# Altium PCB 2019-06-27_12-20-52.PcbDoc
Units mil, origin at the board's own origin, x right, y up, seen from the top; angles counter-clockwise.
Board outline 2660 x 2720 mil, 4 copper layers (Top Layer, MidLayer1, MidLayer2, Bottom Layer); 29 components, 16 nets, 76 pads, 58 vias.
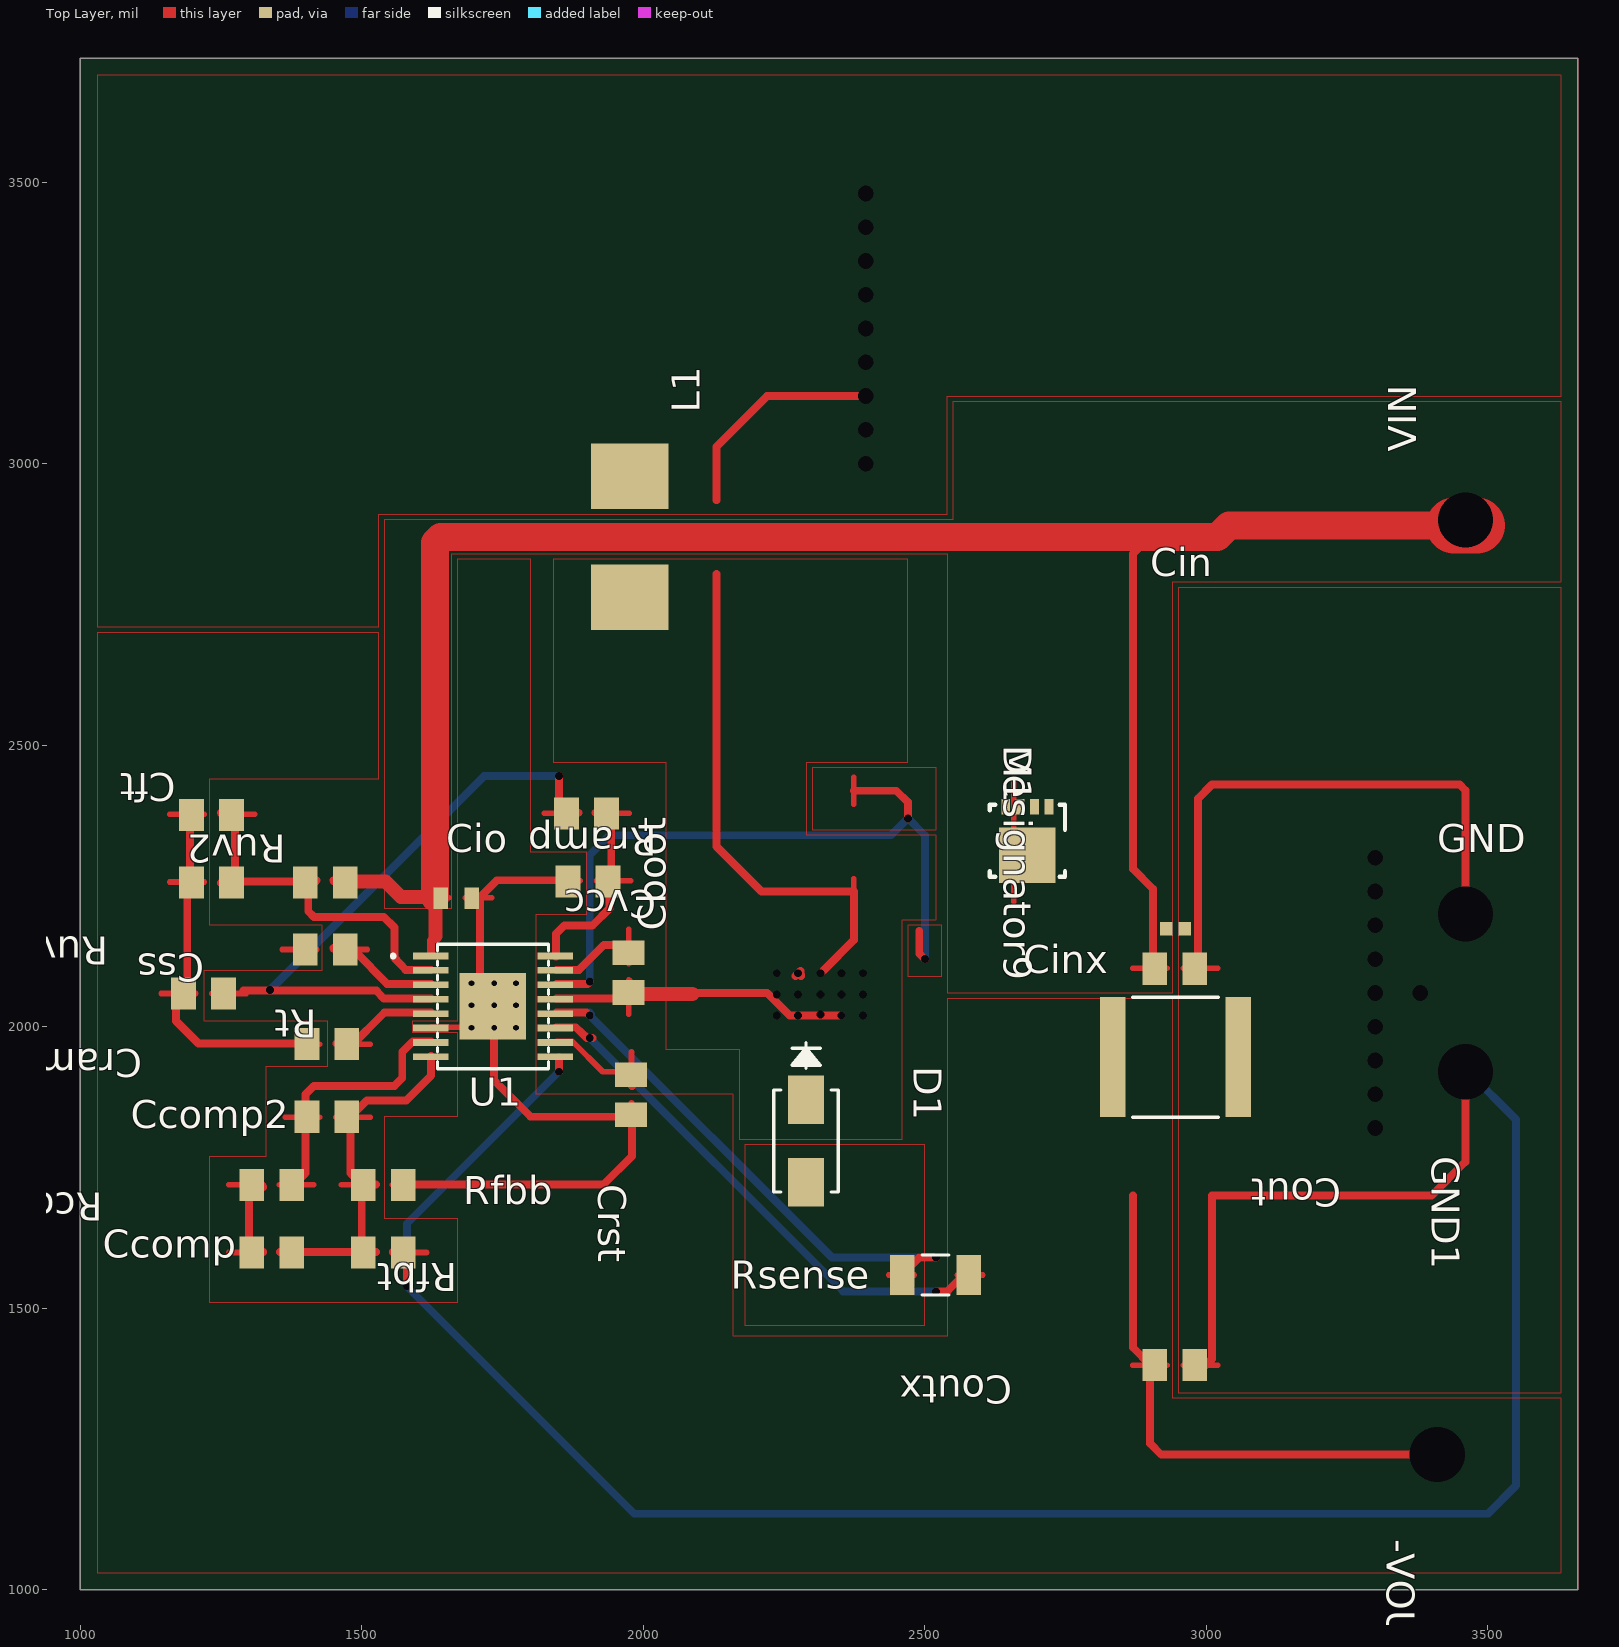
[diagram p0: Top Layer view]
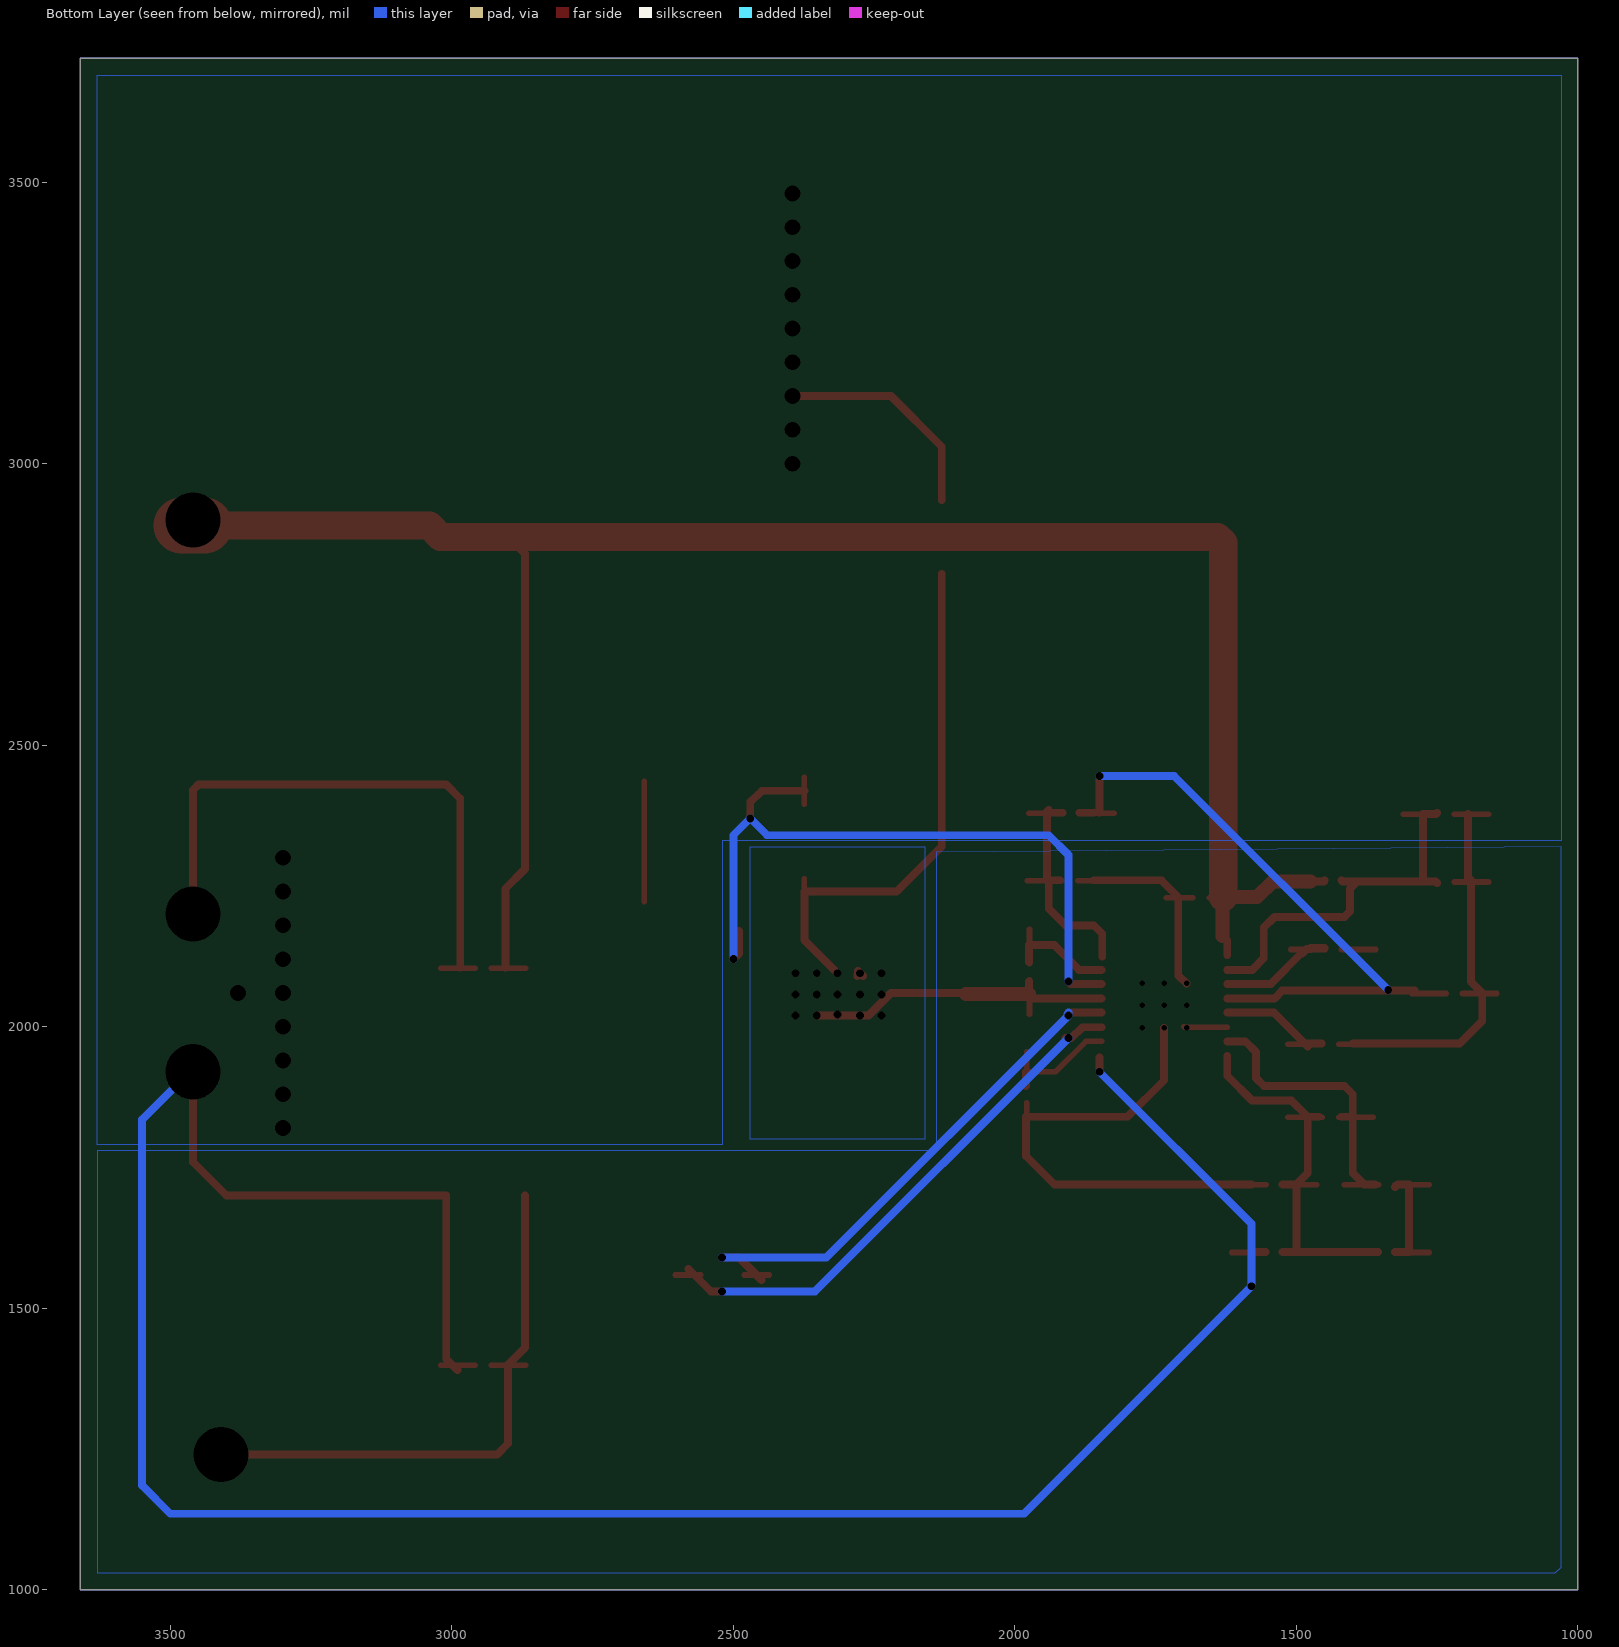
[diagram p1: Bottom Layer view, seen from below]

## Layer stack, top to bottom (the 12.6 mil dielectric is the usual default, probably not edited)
Top Layer: signal copper 1.4
Dielectric: core 12.6, FR-4, Dk 4.8
MidLayer1: signal copper 1.4
Dielectric: prepreg 12.6, FR-4, Dk 4.8
MidLayer2: signal copper 1.4
Dielectric: core 12.6, FR-4, Dk 4.8
Bottom Layer: signal copper 1.4

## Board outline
1000,1000 3660,1000 3660,3720 1000,3720

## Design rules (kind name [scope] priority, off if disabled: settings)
PlaneConnect [All] p0: scope1count=1 scope1_0_kind=Board scope1_0_value=Board scope2count=1 scope2_0_kind=Board scope2_0_value=Board commentlength=0 planeconnectstyle=Direct reliefexpansion=20 reliefentries=4 reliefconductorwidth=10 reliefairgap=10
PlaneConnect [All] p1: planeconnectstyle=Direct reliefexpansion=20 reliefentries=4 reliefconductorwidth=10 reliefairgap=10
PolygonConnect [All] p0: scope1count=1 scope1_0_kind=Board scope1_0_value=Board scope2count=1 scope2_0_kind=Board scope2_0_value=Board commentlength=0 connectstyle=Direct reliefconductorwidth=10 reliefentries=4 polygonreliefangle="90 Angle"
PolygonConnect [All] p1: connectstyle=Direct reliefconductorwidth=10 reliefentries=4 polygonreliefangle="90 Angle"

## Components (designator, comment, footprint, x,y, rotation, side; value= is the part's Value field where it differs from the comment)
-VOUT "" TP-1502 3409,1240 r270 top
Cboot "" 0805 1974,2096 r90 top
Ccomp "" 0805 1340,1599 r0 top
Ccomp2 "" 0805 1438,1840 r0 top
Cft "" 0805 1233,2376 r180 top
Cin "" 0402 2945,2174 r0 top
Cinx "" 0805 2944,2103 r0 top
Cio "" 0603 1668,2228 r0 top
Cout "" 2220_280 2945,1946 r180 top
Coutx "" 0805 2944,1399 r180 top
Cramp "" 0805 1219,2059 r180 top
Crst "" 0805 1978,1879 r270 top
Css "" 0805 1435,2137 r180 top
Cvcc "" 0805 1902,2258 r180 top
D1 "" SMA 2289,1797 r270 top
GND "" TP-1502 3459,2198 r0 top
GND1 "" TP-1502 3459,1918 r270 top
L1 "" WE-LHMI_7030 1976,2870 r90 top
M1 "" DNH0008A 2682,2330 r270 top
Rcomp "" 0805 1340,1719 r180 top
Rfbb "" 0805 1538,1719 r0 top
Rfbt "" 0805 1538,1599 r180 top
Rramp "" 0805 1899,2379 r180 top
Rsense "" 1206 2519,1559 r0 top
Rt "" 0805 1438,1969 r180 top
Ruv1 "" 0805 1233,2256 r180 top
Ruv2 "" 0805 1435,2256 r180 top
U1 "" MXA16A 1733,2036 r0 top
VIN "" TP-1502 3459,2899 r90 top

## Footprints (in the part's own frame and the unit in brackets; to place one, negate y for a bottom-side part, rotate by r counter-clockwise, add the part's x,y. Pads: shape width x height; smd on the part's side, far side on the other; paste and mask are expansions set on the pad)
0402 [mil]
  rect 22x24 smd: 1(-16.5,0) 2(16.5,0)
0603 [mil]
  rect 26x38 smd: 1(-27.5,0) 2(27.5,0)
0805 [mil]
  rect 44x57 smd: 1(-35.5,0) 2(35.5,0)
1206 [mil]
  rect 44x71 smd: 1(-59,0) 2(59,0)
  silkscreen extent -24,-36 24,36
2220_280 [mil]
  rect 45x213 smd: 1(-111.5,0) 2(111.5,0)
  silkscreen extent -76,-107 76,107
DNH0008A [mm]
  rect 0.7x0.4 smd: 1(-1.55,0.975) 2(-1.55,0.325) 3(-1.55,-0.325) 4(-1.55,-0.975) 5(1.55,-0.975) 6(1.55,-0.325) 7(1.55,0.325) 8(1.55,0.975)
  rect 2.51x2.55 smd: 9(0.645,0)
  silkscreen extent -1.62,-1.7 1.62,1.7
MXA16A [mm]
  rect 1.6x0.3 smd: 1(-2.8,2.275) 2(-2.8,1.625) 3(-2.8,0.975) 4(-2.8,0.325) 5(-2.8,-0.325) 6(-2.8,-0.975) 7(-2.8,-1.625) 8(-2.8,-2.275) 9(2.8,-2.275) 10(2.8,-1.625) 11(2.8,-0.975) 12(2.8,-0.325) 13(2.8,0.325) 14(2.8,0.975) 15(2.8,1.625) 16(2.8,2.275)
  rect 3x3 smd: 17(0,0)
  silkscreen extent -4.58,-2.8 2.5,2.8
SMA [mil]
  rect 86x64 smd: 1(-73,0) 2(73,0)
  silkscreen extent -174,-58 91,58
TP-1502 [mil]
  round 65 / inner round 0 / far side round 65 hole 32: 1(0,0)
WE-LHMI_7030 [mm]
  rect 2.95x3.5 smd: 1(-2.725,0) 2(2.725,0)

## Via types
v1: diameter 0, hole 14, Top Layer to Bottom Layer, 26 vias
v2: diameter 0, hole 28, Top Layer to Bottom Layer, 19 vias
v3: diameter 0, hole 10, Top Layer to Bottom Layer, 9 vias
v4: diameter 0, hole 98, Top Layer to Bottom Layer, 4 vias

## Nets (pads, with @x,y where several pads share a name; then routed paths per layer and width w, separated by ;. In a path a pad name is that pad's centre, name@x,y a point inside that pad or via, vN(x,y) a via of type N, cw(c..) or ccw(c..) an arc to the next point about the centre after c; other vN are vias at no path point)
0: -VOUT.1 Cft.2 Cio.2 Cout.2 Coutx.2 Cramp.2 Crst.2 Css.2 Cvcc.2 Rfbb.2 Rsense.2 Rt.2 Ruv1.2 U1.6 U1.11 U1.17 | length 4451.2
  Top Layer w10: 1144,2059 Cramp.2@1205,2059 ; 1159,2257 1220,2257 ; 1159,2377 1220,2377 ; 1359,2137 Css.2@1420,2137 ; 1364,1969 1425,1969 ; Rfbb.2@1554,1719 1615,1719 ; U1.6@1623,1999 1699,1999 U1.17@1700,2000 ; Cio.2@1684,2229 1731,2229 ; 1827,2259 Cvcc.2@1888,2259 ; 1979,1804 Crst.2@1979,1865 ; Rsense.2@2558,1559 2603,1559 ; 2869,1399 Coutx.2@2930,1399
  Top Layer w14: Cft.2@1195,2378 1195,2265 1190,2260 1190,2080 1170,2060 1170,2010 1210,1970 Rt.2@1400,1970 ; Rfbb.2@1580,1720 1930,1720 1980,1770 1980,1840 1800,1840 1735,1905 v3(1735,1998) ; v3(1695,2077) 1710,2091 1710,2230 1740,2260 Cvcc.2@1860,2260 ; U1.11@1846,1999 1880,1999 1900,1980 v1(1905,1980) 1910,1980 ; v1(2520,1530) 2540,1530 Rsense.2@2580,1570 ; 2870,1700 2870,1430 2900,1400 2900,1260 2920,1240 v4(3410,1240) -VOUT.1@3420,1240
  Bottom Layer w14: v1(1905,1980) 2355,1530 v1(2520,1530)
  other v3: 1695,1998 1774,1998 1695,2038 1735,2038 1774,2038 1735,2077 1774,2077
1: Ccomp2.2 Ccomp.2 Rfbb.1 Rfbt.2 U1.8 | length 915.5
  Top Layer w10: Ccomp.2@1354,1599 1415,1599 ; Ccomp2.2@1454,1839 1515,1839 ; 1464,1599 1525,1599 ; 1464,1719 1525,1719
  Top Layer w14: Ccomp.2@1355,1600 1380,1600 Rfbt.2@1500,1600 ; Ccomp2.2@1460,1840 Ccomp2.2@1480,1840 ; 1525,1600 Rfbt.2@1500,1600 ; 1525,1720 Rfbb.1@1500,1720 ; U1.8@1623,1948 1623,1913 1579,1869 1509,1869 Ccomp2.2@1480,1840 ; Ccomp2.2@1480,1840 1480,1740 Rfbb.1@1500,1720 ; Rfbt.2@1500,1600 Rfbb.1@1500,1720
2: Ccomp2.1 Rcomp.1 U1.7 | length 619.2
  Top Layer w10: Rcomp.1@1354,1719 1415,1719 ; 1364,1839 1425,1839
  Top Layer w14: Rcomp.1@1360,1720 1380,1720 1400,1740 Ccomp2.1@1400,1840 ; Ccomp2.1@1420,1840 Ccomp2.1@1400,1840 ; U1.7@1623,1974 1591,1974 1572,1955 1572,1909 1558,1895 1415,1895 1400,1880 Ccomp2.1@1400,1840
3: Cin.1 Cinx.1 Cio.1 M1.5 M1.6 M1.7 M1.8 M1.9 Ruv2.1 U1.1 VIN.1 | length 3966.1
  Top Layer w10: Ruv2.1@1449,2257 1510,2257 ; 1608,2229 1655,2229 ; 2658,2222 2658,2436 ; 2869,2104 Cinx.1@2930,2104
  Top Layer w14: Ruv2.1@1450,2260 1452,2258 Ruv2.1@1475,2258 ; U1.1@1623,2127 1623,2153 1631,2161 ; 2900,2870 2870,2840 2870,2420 2870,2280 2905,2245 Cinx.1@2905,2105
  Top Layer w25: Ruv2.1@1475,2258 1542,2258 1570,2230 Cio.1@1630,2230 ; 1631,2161 Cio.1@1631,2230
  Top Layer w50: Cio.1@1630,2230 1630,2750 1630,2860 1640,2870 1750,2870 2900,2870 3020,2870 3040,2890 VIN.1@3440,2890
  Top Layer w100: VIN.1@3440,2890 VIN.1@3480,2890
  other v4: 3460,2900
4: Crst.1 U1.10 | length 242.4
  Top Layer w10: U1.10@1846,1974 1874,1974 1928,1920 Crst.1@1980,1920 ; Crst.1@1979,1894 1979,1955
  Top Layer w14: Crst.1@1980,1895 Crst.1@1980,1920
5: Cin.2 Cinx.2 Cout.1 Coutx.1 GND1.1 GND.1 L1.2 Rfbt.1 U1.9 | length 6074
  Top Layer w10: Rfbt.1@1554,1599 1615,1599 ; Coutx.1@2959,1399 3020,1399 ; Cinx.2@2959,2104 3020,2104
  Top Layer w14: Rfbt.1@1555,1600 1580,1600 1580,1540 ; v1(1850,1920) U1.9@1850,1945 ; 2130,2935 2130,3030 2220,3120 v2(2395,3120) ; Cinx.2@2985,2105 2985,2405 3010,2430 3450,2430 3460,2420 v4(3460,2200) ; Coutx.1@2990,1390 3010,1410 3010,1700 3400,1700 3460,1760 v4(3460,1920)
  Bottom Layer w14: v1(1850,1920) 1580,1650 v1(1580,1539) 1984,1135 3500,1135 3550,1185 3550,1835 GND1.1@3465,1920
  other v2: 3300,1820 3300,1880 3300,1940 3300,2000 3300,2060 3380,2060 3300,2120 3300,2180 3300,2240 3300,2300 2395,3000 2395,3060 2395,3180 2395,3240 2395,3300 2395,3360 2395,3420 2395,3480
6: Cft.1 Ruv1.1 Ruv2.2 U1.2 | length 849.3
  Top Layer w10: Ruv1.1@1249,2257 1310,2257 ; Cft.1@1249,2377 1310,2377 ; 1359,2257 Ruv2.2@1420,2257
  Top Layer w14: Ruv1.1@1250,2255 1253,2258 Ruv1.1@1275,2258 ; Cft.1@1250,2380 1252,2378 1275,2378 Ruv1.1@1275,2258 ; Ruv2.2@1395,2258 1418,2258 Ruv2.2@1420,2260 ; U1.2@1623,2101 1578,2101 1558,2122 1558,2176 1539,2195 1415,2195 1405,2205 1405,2245 1392,2258 Ruv1.1@1275,2258
7: Cvcc.1 Rramp.1 U1.16 | length 501.1
  Top Layer w10: Rramp.1@1914,2379 1975,2379 ; Cvcc.1@1917,2259 1978,2259
  Top Layer w14: U1.16@1845,2125 1845,2165 1860,2180 1910,2180 1940,2210 Cvcc.1@1940,2260 ; Rramp.1@1915,2380 Rramp.1@1940,2380 ; Cvcc.1@1920,2260 Cvcc.1@1940,2260 ; Rramp.1@1940,2385 1943,2382 1943,2263 Cvcc.1@1940,2260 ; Cvcc.1@1943,2260 Cvcc.1@1940,2260
8: Cramp.1 Rramp.2 U1.4 | length 1221.5
  Top Layer w10: Cramp.1@1234,2059 1295,2059 ; 1824,2379 Rramp.2@1885,2379
  Top Layer w14: 1290,2064 1526,2064 1539,2050 U1.4@1623,2050 ; Rramp.2@1850,2380 v1(1850,2445) ; Rramp.2@1860,2380 Rramp.2@1885,2380
  Bottom Layer w14: v1(1337,2065) 1717,2445 v1(1850,2445)
9: Rt.1 U1.5 | length 253.9
  Top Layer w10: Rt.1@1454,1969 1515,1969
  Top Layer w14: Rt.1@1455,1970 Rt.1@1480,1970 ; Rt.1@1480,1965 1540,2025 U1.5@1623,2025
10: Css.1 U1.3 | length 264.2
  Top Layer w10: Css.1@1449,2137 1510,2137
  Top Layer w14: Css.1@1450,2140 1475,2140 1475,2138 1482,2138 Css.1@1490,2130 ; Css.1@1489,2133 1545,2076 U1.3@1623,2076
11: D1.2 Rsense.1 U1.12 | length 989.1
  Top Layer w10: 2436,1559 Rsense.1@2481,1559
  Top Layer w14: U1.12@1846,2025 1899,2025 v1(1905,2020) ; Rsense.1@2450,1550 2490,1590 v1(2520,1590)
  Bottom Layer w14: v1(1905,2020) 2335,1590 v1(2520,1590) ; 1905,2025 1907,2022
12: M1.4 U1.14 | length 1375.1
  Top Layer w10: 2374,2395 2374,2443
  Top Layer w14: U1.14@1846,2076 1901,2076 v1(1905,2080) ; 2374,2419 2449,2419 2470,2399 v1(2470,2370) ; 2490,2170 2490,2130 v1(2500,2120)
  Bottom Layer w14: v1(1905,2080) 1905,2305 1940,2340 2440,2340 v1(2470,2370) 2500,2340 v1(2500,2120)
13: Cboot.1 D1.1 L1.1 M1.1 M1.2 M1.3 U1.13 | length 1603.7
  Top Layer w10: 1974,2022 1974,2083 ; 2374,2215 2374,2263
  Top Layer w14: U1.13@1846,2050 Cboot.1@1974,2050 ; Cboot.1@1975,2058 Cboot.1@1975,2080 ; 2080,2060 2089,2060 ; 2087,2058 2089,2060 ; 2130,2804 2130,2320 2210,2240 2370,2240 ; 2270,2090 v1(2275,2095) 2279,2099 2280,2090 ; 2320,2100 2374,2154 2374,2240 ; v1(2352,2020) 2260,2020 2220,2060 2089,2060
  Top Layer w25: Cboot.1@1975,2058 2087,2058
  other v1: 2237,2020 2275,2020 2390,2020 2315,2022 2237,2057 2275,2057 2315,2057 2352,2057 2390,2057 2237,2095 2315,2095 2352,2095 2390,2095
14: Cboot.2 U1.15 | length 231.2
  Top Layer w10: Cboot.2@1974,2112 1974,2173
  Top Layer w14: U1.15@1846,2101 1886,2101 1930,2145 Cboot.2@1975,2145 ; Cboot.2@1975,2115 Cboot.2@1975,2138
15: Ccomp.1 Rcomp.2 | length 294.1
  Top Layer w10: 1264,1599 Ccomp.1@1325,1599 ; 1264,1719 Rcomp.2@1325,1719
  Top Layer w14: Ccomp.1@1325,1600 1300,1600 1300,1720 1320,1720 Rcomp.2@1325,1715

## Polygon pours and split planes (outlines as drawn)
12 on Top Layer " " (solid, pour order 0): 2470,2180 2470,2090 2530,2090 2530,2180
12 on Top Layer " " (solid, pour order 1): 2300,2460 2300,2350 2520,2350 2520,2460
5 on Top Layer " " (solid, pour order 2): 2950,2780 2950,1350 3630,1350 3630,2780
11 on Top Layer " " (solid, pour order 3): 2180,1790 2180,1470 2500,1470 2500,1630 2500,1790
13 on Top Layer " " (solid, pour order 4): 1840,2830 1840,2470 2040,2470 2040,1960 2170,1960 2170,1800 2460,1800 2460,2190 2520,2190 2520,2340 2290,2340 2290,2470 2470,2470 2470,2830
3 on Top Layer " " (solid, pour order 5): 2540,2060 2940,2060 2940,2790 3630,2790 3630,3110 2550,3110 2550,2900 1540,2900 1540,2210 1660,2210 1660,2840 2540,2840
5 on Top Layer " " (solid, pour order 6): 1030,3690 1030,2710 1530,2710 1530,2910 2540,2910 2540,3120 3630,3120 3630,3690
0 on Top Layer " " (solid, pour order 9): 1030,2700 1030,1030 3630,1030 3630,1340 2940,1340 2940,2050 2540,2050 2540,1450 2160,1450 2160,1880 1810,1880 1810,2200 1900,2200 1900,2310 1800,2310 1800,2830 1670,2830 1670,2010 1590,2010 1590,1990 1670,1990 1670,1840 1540,1840 1540,1660 1670,1660 1670,1510 1230,1510 1230,1770 1330,1770 1330,1930 1440,1930 1440,2010 1220,2010 1220,2100 1430,2100 1430,2180 1230,2180 1230,2440 1530,2440 1530,2700
13 on Bottom Layer " " (solid, pour order 7): 2160,2320 2160,1800 2470,1800 2470,2320
5 on Bottom Layer " " (solid, pour order 8): 1030,2330 2520,2330 2520,1790 3630,1790 3630,3690 1030,3690
0 on Bottom Layer " " (solid, pour order 10): 1030,2320 2140,2310 2140,1780 3630,1780 3630,1030 1040,1030 1030,1040
no net on Top Paste "Top Layer-No Net" (solid, remove dead copper): 1812.72,2002.54 1812.72,1992.69 1873.75,1992.69 1873.75,2002.54
no net on Top Paste "Top Layer-No Net" (solid, remove dead copper): 1812.72,2028.13 1812.72,2018.28 1873.75,2018.28 1873.75,2028.13
no net on Top Paste "Top Layer-No Net" (solid, remove dead copper): 1812.72,2053.72 1812.72,2043.87 1873.75,2043.87 1873.75,2053.72
no net on Top Paste "Top Layer-No Net" (solid, remove dead copper): 1812.72,2079.31 1812.72,2069.46 1873.75,2069.46 1873.75,2079.31
no net on Top Paste "Top Layer-No Net" (solid, remove dead copper): 1812.72,2104.9 1812.72,2095.05 1873.75,2095.05 1873.75,2104.9
no net on Top Paste "Top Layer-No Net" (solid, remove dead copper): 1812.72,2130.49 1812.72,2120.64 1873.75,2120.64 1873.75,2130.49
no net on Top Solder "Top Layer-No Net" (solid, remove dead copper): 1591.27,2131.47 1591.27,2119.66 1654.26,2119.66 1654.26,2131.47
no net on Top Solder "Top Layer-No Net" (solid, remove dead copper): 1591.27,2105.88 1591.27,2094.07 1654.26,2094.07 1654.26,2105.88
no net on Top Solder "Top Layer-No Net" (solid, remove dead copper): 1591.27,2080.29 1591.27,2068.48 1654.26,2068.48 1654.26,2080.29
no net on Top Solder "Top Layer-No Net" (solid, remove dead copper): 1591.27,2054.7 1591.27,2042.89 1654.26,2042.89 1654.26,2054.7
no net on Top Solder "Top Layer-No Net" (solid, remove dead copper): 1591.27,2029.11 1591.27,2017.3 1654.26,2017.3 1654.26,2029.11
no net on Top Solder "Top Layer-No Net" (solid, remove dead copper): 1591.27,2003.52 1591.27,1991.71 1654.26,1991.71 1654.26,2003.52
no net on Top Solder "Top Layer-No Net" (solid, remove dead copper): 1591.27,1977.93 1591.27,1966.12 1654.26,1966.12 1654.26,1977.93
no net on Top Solder "Top Layer-No Net" (solid, remove dead copper): 1591.27,1952.34 1591.27,1940.53 1654.26,1940.53 1654.26,1952.34
no net on Top Solder "Top Layer-No Net" (solid, remove dead copper): 1811.74,1952.34 1811.74,1940.53 1874.73,1940.53 1874.73,1952.34
no net on Top Solder "Top Layer-No Net" (solid, remove dead copper): 1811.74,1977.93 1811.74,1966.12 1874.73,1966.12 1874.73,1977.93
no net on Top Solder "Top Layer-No Net" (solid, remove dead copper): 1811.74,2003.52 1811.74,1991.71 1874.73,1991.71 1874.73,2003.52
no net on Top Solder "Top Layer-No Net" (solid, remove dead copper): 1811.74,2029.11 1811.74,2017.3 1874.73,2017.3 1874.73,2029.11
no net on Top Solder "Top Layer-No Net" (solid, remove dead copper): 1811.74,2054.7 1811.74,2042.89 1874.73,2042.89 1874.73,2054.7
no net on Top Solder "Top Layer-No Net" (solid, remove dead copper): 1811.74,2080.29 1811.74,2068.48 1874.73,2068.48 1874.73,2080.29
no net on Top Solder "Top Layer-No Net" (solid, remove dead copper): 1811.74,2105.88 1811.74,2094.07 1874.73,2094.07 1874.73,2105.88
no net on Top Solder "Top Layer-No Net" (solid, remove dead copper): 1811.74,2131.47 1811.74,2119.66 1874.73,2119.66 1874.73,2131.47
no net on Top Paste "Top Layer-No Net" (solid, remove dead copper): 1677.88,2091.12 1677.88,2039.94 1729.06,2039.94 1729.06,2091.12
no net on Top Paste "Top Layer-No Net" (solid, remove dead copper): 1677.88,2032.06 1677.88,1980.88 1729.06,1980.88 1729.06,2032.06
no net on Top Paste "Top Layer-No Net" (solid, remove dead copper): 1736.94,2091.12 1736.94,2039.94 1788.12,2039.94 1788.12,2091.12
no net on Top Paste "Top Layer-No Net" (solid, remove dead copper): 1736.94,2032.06 1736.94,1980.88 1788.12,1980.88 1788.12,2032.06
no net on Top Layer "Top Layer-No Net" (solid, remove dead copper): 1733,2095.06
no net on Top Layer "Top Layer-No Net" (solid, remove dead copper): 1733,1976.94
no net on Top Solder "Top Layer-No Net" (solid, remove dead copper): 1733,2095.06
no net on Top Solder "Top Layer-No Net" (solid, remove dead copper): 1733,1976.94
no net on Top Solder "Top Layer-No Net" (solid, remove dead copper): 2714.48,2293.58 2714.48,2273.9 2726.29,2273.9 2726.29,2293.58
no net on Top Solder "Top Layer-No Net" (solid, remove dead copper): 2637.71,2293.58 2637.71,2273.9 2649.52,2273.9 2649.52,2293.58
no net on Top Solder "Top Layer-No Net" (solid, remove dead copper): 2663.3,2293.58 2663.3,2273.9 2675.11,2273.9 2675.11,2293.58
no net on Top Solder "Top Layer-No Net" (solid, remove dead copper): 2688.89,2293.58 2688.89,2273.9 2700.7,2273.9 2700.7,2293.58
no net on Top Paste "Top Layer-No Net" (solid, remove dead copper): 2728.29,2324.29 2687.88,2324.29 2687.5,2324.33 2687.14,2324.44 2686.8,2324.62 2686.51,2324.86 2686.26,2325.15 2686.08,2325.49 2685.97,2325.86 2685.94,2326.23 2685.94,2350.1 2685.97,2350.48 2686.08,2350.85 2686.26,2351.18 2686.51,2351.48 2686.8,2351.72 2687.14,2351.9 2687.5,2352.01 2687.88,2352.05 2728.29,2352.05 2728.66,2352.01 2729.03,2351.9 2729.36,2351.72 2729.66,2351.48 2729.9,2351.18 2730.08,2350.85 2730.19,2350.48 2730.23,2350.1 2730.23,2326.23 2730.19,2325.86 2730.08,2325.49 2729.9,2325.15 2729.66,2324.86 2729.36,2324.62 2729.03,2324.44 2728.66,2324.33
no net on Top Paste "Top Layer-No Net" (solid, remove dead copper): 2676.12,2324.29 2635.71,2324.29 2635.34,2324.33 2634.97,2324.44 2634.64,2324.62 2634.34,2324.86 2634.1,2325.15 2633.92,2325.49 2633.81,2325.86 2633.77,2326.23 2633.77,2350.1 2633.81,2350.48 2633.92,2350.85 2634.1,2351.18 2634.34,2351.48 2634.64,2351.72 2634.97,2351.9 2635.34,2352.01 2635.71,2352.05 2676.12,2352.05 2676.5,2352.01 2676.86,2351.9 2677.2,2351.72 2677.49,2351.48 2677.74,2351.18 2677.92,2350.85 2678.03,2350.48 2678.06,2350.1 2678.06,2326.23 2678.03,2325.86 2677.92,2325.49 2677.74,2325.15 2677.49,2324.86 2677.2,2324.62 2676.86,2324.44 2676.5,2324.33
no net on Top Paste "Top Layer-No Net" (solid, remove dead copper): 2635.71,2316.42 2676.12,2316.42 2676.5,2316.38 2676.86,2316.27 2677.2,2316.09 2677.49,2315.85 2677.74,2315.55 2677.92,2315.22 2678.03,2314.85 2678.06,2314.47 2678.06,2290.6 2678.03,2290.23 2677.92,2289.86 2677.74,2289.52 2677.49,2289.23 2677.2,2288.99 2676.86,2288.81 2676.5,2288.7 2676.12,2288.66 2635.71,2288.66 2635.34,2288.7 2634.97,2288.81 2634.64,2288.99 2634.34,2289.23 2634.1,2289.52 2633.92,2289.86 2633.81,2290.23 2633.77,2290.6 2633.77,2314.47 2633.81,2314.85 2633.92,2315.22 2634.1,2315.55 2634.34,2315.85 2634.64,2316.09 2634.97,2316.27 2635.34,2316.38
no net on Top Paste "Top Layer-No Net" (solid, remove dead copper): 2687.88,2316.42 2728.29,2316.42 2728.66,2316.38 2729.03,2316.27 2729.36,2316.09 2729.66,2315.85 2729.9,2315.55 2730.08,2315.22 2730.19,2314.85 2730.23,2314.47 2730.23,2290.6 2730.19,2290.23 2730.08,2289.86 2729.9,2289.52 2729.66,2289.23 2729.36,2288.99 2729.03,2288.81 2728.66,2288.7 2728.29,2288.66 2687.88,2288.66 2687.5,2288.7 2687.14,2288.81 2686.8,2288.99 2686.51,2289.23 2686.26,2289.52 2686.08,2289.86 2685.97,2290.23 2685.94,2290.6 2685.94,2314.47 2685.97,2314.85 2686.08,2315.22 2686.26,2315.55 2686.51,2315.85 2686.8,2316.09 2687.14,2316.27 2687.5,2316.38
no net on Top Solder "Top Layer-No Net" (solid, remove dead copper): 2635.87,2352.05 2728.13,2352.05 2728.54,2352.01 2728.93,2351.89 2729.3,2351.69 2729.61,2351.43 2729.88,2351.12 2730.07,2350.75 2730.19,2350.36 2730.23,2349.95 2730.23,2284.26 2730.19,2283.85 2730.07,2283.46 2729.88,2283.1 2729.61,2282.78 2729.3,2282.52 2728.93,2282.32 2728.54,2282.21 2728.13,2282.17 2635.87,2282.17 2635.46,2282.21 2635.07,2282.32 2634.7,2282.52 2634.39,2282.78 2634.12,2283.1 2633.93,2283.46 2633.81,2283.85 2633.77,2284.26 2633.77,2349.95 2633.81,2350.36 2633.93,2350.75 2634.12,2351.12 2634.39,2351.43 2634.7,2351.69 2635.07,2351.89 2635.46,2352.01

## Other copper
Multi-Layer:
  the board outline again, w1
